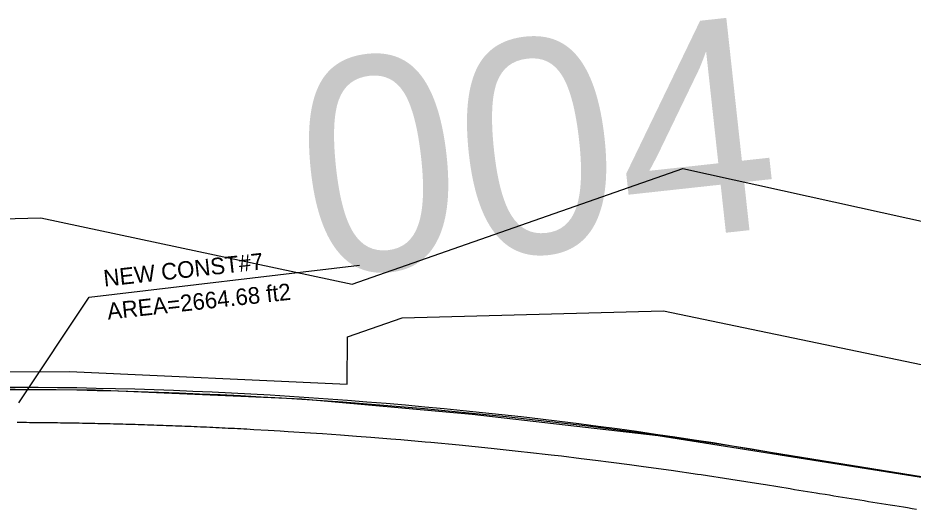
# Model space of a CAD drawing. Extents: x 1509538 to 1510847, y 401283 to 402022.
# Drawn here: x 1510184.5 to 1510335.3, y 401706.3 to 401789.3 of the extents above; entities that cross this region are included whole.
import ezdxf

# ---------------------------------------------------------------- set-up
doc = ezdxf.new("R2010")
doc.units = 0
for name, color, linetype in [('LAWE_P_T', 7, 'Continuous'), ('Level 14', 7, 'Continuous'), ('Level 22', 7, 'Continuous'), ('Level 24', 7, 'Continuous'), ('Level 3', 7, 'Continuous')]:
    doc.layers.add(name, color=color, linetype=linetype)

msp = doc.modelspace()

# ---------------------------------------------------------------- linework, layer by layer
at = {"layer": 'LAWE_P_T'}
msp.add_lwpolyline([(1510184.66, 401724.34), (1510196.5, 401742.17), (1510242.07, 401747.56)], dxfattribs=at)
at = {"layer": 'Level 14'}
msp.add_line((1510311.33, 401716), (1510436.45, 401695.69), dxfattribs=at)
msp.add_arc((1510179.87, 400906.1), 820.5, 80.78048, 96.2219, dxfattribs=at)
at = {"layer": 'Level 22'}
msp.add_lwpolyline([(1510163.27, 401729.57), (1510193.23, 401729.63), (1510240, 401727.48), (1510240.05, 401735.46), (1510249.26, 401738.71), (1510293.27, 401739.88), (1510404.63, 401716.65), (1510416.62, 401714.21), (1510414.07, 401699.18), (1510406.28, 401635.45), (1510397.88, 401621.86), (1510377.81, 401611.86), (1510331.03, 401618.95), (1510273.83, 401631.15), (1510231.99, 401640.14), (1510237.83, 401669.36), (1510405.63, 401640.09), (1510412.68, 401699.55), (1510362.56, 401707.65), (1510292.37, 401718.82), (1510261.04, 401722.38), (1510232.33, 401724.97), (1510197.61, 401726.48), (1510164.02, 401726.59)], dxfattribs=at)
at = {"layer": 'Level 24'}
msp.add_lwpolyline([(1509965.11, 401725.82), (1510041.03, 401773.36), (1510042.45, 401774.24), (1510071.47, 401767.53), (1510092.26, 401761.29), (1510106.06, 401761.59), (1510116.39, 401753.93), (1510166.17, 401754.62), (1510168.79, 401755.02), (1510188.36, 401755.57), (1510240.81, 401744.39), (1510296.54, 401763.85), (1510359.87, 401749.85), (1510436.07, 401732.12)], dxfattribs=at)
at = {"layer": 'Level 3'}
for p, q in [((1510184.39, 401721.09), (1510184.91, 401721.09)), ((1510184.91, 401721.09), (1510185.43, 401721.08)), ((1510185.43, 401721.08), (1510185.96, 401721.08)), ((1510185.96, 401721.08), (1510186.48, 401721.07)), ((1510186.48, 401721.07), (1510187, 401721.07)), ((1510187, 401721.07), (1510187.53, 401721.07)), ((1510187.53, 401721.07), (1510188.05, 401721.06)), ((1510188.05, 401721.06), (1510188.57, 401721.05)), ((1510188.57, 401721.05), (1510189.1, 401721.05)), ((1510189.1, 401721.05), (1510189.62, 401721.04)), ((1510189.62, 401721.04), (1510190.14, 401721.04)), ((1510190.14, 401721.04), (1510190.67, 401721.03)), ((1510190.67, 401721.03), (1510191.19, 401721.02)), ((1510191.19, 401721.02), (1510191.71, 401721.01)), ((1510191.71, 401721.01), (1510192.24, 401721.01)), ((1510192.24, 401721.01), (1510192.76, 401721)), ((1510192.76, 401721), (1510193.28, 401720.99)), ((1510193.28, 401720.99), (1510193.81, 401720.98)), ((1510193.81, 401720.98), (1510194.33, 401720.97)), ((1510194.33, 401720.97), (1510194.86, 401720.96)), ((1510194.86, 401720.96), (1510195.38, 401720.95)), ((1510195.38, 401720.95), (1510195.9, 401720.94)), ((1510195.9, 401720.94), (1510196.43, 401720.93)), ((1510196.43, 401720.93), (1510196.95, 401720.92)), ((1510196.95, 401720.92), (1510197.47, 401720.91)), ((1510197.47, 401720.91), (1510198, 401720.9)), ((1510198, 401720.9), (1510198.52, 401720.89)), ((1510198.52, 401720.89), (1510199.04, 401720.88)), ((1510199.04, 401720.88), (1510199.57, 401720.86)), ((1510199.57, 401720.86), (1510200.09, 401720.85)), ((1510200.09, 401720.85), (1510200.61, 401720.84)), ((1510200.61, 401720.84), (1510201.14, 401720.82)), ((1510201.14, 401720.82), (1510201.66, 401720.81)), ((1510201.66, 401720.81), (1510202.18, 401720.8)), ((1510202.18, 401720.8), (1510202.7, 401720.78)), ((1510202.7, 401720.78), (1510203.23, 401720.77)), ((1510203.23, 401720.77), (1510203.75, 401720.75)), ((1510203.75, 401720.75), (1510204.27, 401720.74)), ((1510204.27, 401720.74), (1510204.8, 401720.72)), ((1510204.8, 401720.72), (1510205.32, 401720.7)), ((1510205.32, 401720.7), (1510205.84, 401720.69)), ((1510205.84, 401720.69), (1510206.37, 401720.67)), ((1510206.37, 401720.67), (1510206.89, 401720.65)), ((1510206.89, 401720.65), (1510207.41, 401720.64)), ((1510207.41, 401720.64), (1510207.94, 401720.62)), ((1510207.94, 401720.62), (1510208.46, 401720.6)), ((1510208.46, 401720.6), (1510208.98, 401720.58)), ((1510208.98, 401720.58), (1510209.51, 401720.56)), ((1510209.51, 401720.56), (1510210.03, 401720.54)), ((1510210.03, 401720.54), (1510210.55, 401720.52)), ((1510210.55, 401720.52), (1510211.08, 401720.5)), ((1510211.08, 401720.5), (1510211.6, 401720.48)), ((1510211.6, 401720.48), (1510212.12, 401720.46)), ((1510212.12, 401720.46), (1510212.64, 401720.44)), ((1510212.64, 401720.44), (1510213.17, 401720.42)), ((1510213.17, 401720.42), (1510213.69, 401720.4)), ((1510213.69, 401720.4), (1510214.21, 401720.38)), ((1510214.21, 401720.38), (1510214.74, 401720.35)), ((1510214.74, 401720.35), (1510215.26, 401720.33)), ((1510215.26, 401720.33), (1510215.78, 401720.31)), ((1510215.78, 401720.31), (1510216.31, 401720.29)), ((1510216.31, 401720.29), (1510216.83, 401720.26)), ((1510216.83, 401720.26), (1510217.35, 401720.24)), ((1510217.35, 401720.24), (1510217.87, 401720.22)), ((1510217.87, 401720.22), (1510218.4, 401720.19)), ((1510218.4, 401720.19), (1510218.92, 401720.16)), ((1510218.92, 401720.16), (1510219.44, 401720.14)), ((1510219.44, 401720.14), (1510219.97, 401720.11)), ((1510219.97, 401720.11), (1510220.49, 401720.09)), ((1510220.49, 401720.09), (1510221.01, 401720.06)), ((1510221.01, 401720.06), (1510221.53, 401720.04)), ((1510221.53, 401720.04), (1510222.06, 401720.01)), ((1510222.06, 401720.01), (1510222.58, 401719.98)), ((1510222.58, 401719.98), (1510223.1, 401719.95)), ((1510223.1, 401719.95), (1510223.63, 401719.93)), ((1510223.63, 401719.93), (1510224.29, 401719.89)), ((1510224.29, 401719.89), (1510226.68, 401719.76)), ((1510226.68, 401719.76), (1510228.71, 401719.64)), ((1510228.71, 401719.64), (1510230.06, 401719.55)), ((1510230.06, 401719.55), (1510233.79, 401719.32)), ((1510233.79, 401719.32), (1510235.83, 401719.18)), ((1510235.83, 401719.18), (1510238.88, 401718.96)), ((1510238.88, 401718.96), (1510241.59, 401718.76)), ((1510241.59, 401718.76), (1510243.96, 401718.58)), ((1510243.96, 401718.58), (1510247.36, 401718.3)), ((1510247.36, 401718.3), (1510249.03, 401718.16)), ((1510249.03, 401718.16), (1510253.11, 401717.8)), ((1510253.11, 401717.8), (1510254.11, 401717.71)), ((1510254.11, 401717.71), (1510258.87, 401717.26)), ((1510258.87, 401717.26), (1510264.25, 401716.72)), ((1510264.25, 401716.72), (1510269.31, 401716.18)), ((1510269.31, 401716.18), (1510270.37, 401716.06)), ((1510270.37, 401716.06), (1510274.37, 401715.6)), ((1510436.45, 401695.69), (1510311.33, 401716)), ((1510274.37, 401715.6), (1510276.11, 401715.4)), ((1510276.11, 401715.4), (1510279.43, 401715)), ((1510279.43, 401715), (1510281.85, 401714.7)), ((1510281.85, 401714.7), (1510284.48, 401714.36)), ((1510284.48, 401714.36), (1510287.58, 401713.95)), ((1510287.58, 401713.95), (1510289.53, 401713.69)), ((1510289.53, 401713.69), (1510293.3, 401713.17)), ((1510293.3, 401713.17), (1510294.58, 401712.99)), ((1510294.58, 401712.99), (1510299.03, 401712.34)), ((1510299.03, 401712.34), (1510299.62, 401712.26)), ((1510299.62, 401712.26), (1510304.65, 401711.49)), ((1510304.65, 401711.49), (1510309.69, 401710.7)), ((1510309.69, 401710.7), (1510310.45, 401710.57)), ((1510310.45, 401710.57), (1510314.63, 401709.89)), ((1510314.63, 401709.89), (1510315.37, 401709.77)), ((1510315.37, 401709.77), (1510316.1, 401709.65)), ((1510316.1, 401709.65), (1510316.83, 401709.54)), ((1510316.83, 401709.54), (1510317.57, 401709.42)), ((1510317.57, 401709.42), (1510318.3, 401709.3)), ((1510318.3, 401709.3), (1510319.03, 401709.18)), ((1510319.03, 401709.18), (1510319.57, 401709.09)), ((1510319.57, 401709.09), (1510320.5, 401708.94)), ((1510320.5, 401708.94), (1510321.23, 401708.82)), ((1510321.23, 401708.82), (1510321.96, 401708.7)), ((1510321.96, 401708.7), (1510322.7, 401708.59)), ((1510322.7, 401708.59), (1510323.43, 401708.47)), ((1510323.43, 401708.47), (1510324.16, 401708.35)), ((1510324.16, 401708.35), (1510324.9, 401708.23)), ((1510324.9, 401708.23), (1510325.63, 401708.11)), ((1510325.63, 401708.11), (1510326.36, 401707.99)), ((1510326.36, 401707.99), (1510327.1, 401707.87)), ((1510327.1, 401707.87), (1510327.83, 401707.75)), ((1510327.83, 401707.75), (1510328.56, 401707.63)), ((1510328.56, 401707.63), (1510329.29, 401707.51)), ((1510329.29, 401707.51), (1510330.03, 401707.4)), ((1510330.03, 401707.4), (1510330.76, 401707.28)), ((1510330.76, 401707.28), (1510331.49, 401707.16)), ((1510331.49, 401707.16), (1510332.23, 401707.04)), ((1510332.23, 401707.04), (1510332.96, 401706.92)), ((1510332.96, 401706.92), (1510333.69, 401706.8)), ((1510333.69, 401706.8), (1510334.38, 401706.69)), ((1510334.38, 401706.69), (1510335.16, 401706.56)), ((1510335.16, 401706.56), (1510335.89, 401706.44))]:
    msp.add_line(p, q, dxfattribs=at)
msp.add_lwpolyline([(1510184.39, 401721.09), (1510184.91, 401721.09), (1510185.43, 401721.08), (1510185.96, 401721.08), (1510186.48, 401721.07), (1510187, 401721.07), (1510187.53, 401721.07), (1510188.05, 401721.06), (1510188.57, 401721.05), (1510189.1, 401721.05), (1510189.62, 401721.04), (1510190.14, 401721.04), (1510190.67, 401721.03), (1510191.19, 401721.02), (1510191.71, 401721.01), (1510192.24, 401721.01), (1510192.76, 401721), (1510193.28, 401720.99), (1510193.81, 401720.98), (1510194.33, 401720.97), (1510194.86, 401720.96), (1510195.38, 401720.95), (1510195.9, 401720.94), (1510196.43, 401720.93), (1510196.95, 401720.92), (1510197.47, 401720.91), (1510198, 401720.9), (1510198.52, 401720.89), (1510199.04, 401720.88), (1510199.57, 401720.86), (1510200.09, 401720.85), (1510200.61, 401720.84), (1510201.14, 401720.82), (1510201.66, 401720.81), (1510202.18, 401720.8), (1510202.7, 401720.78), (1510203.23, 401720.77), (1510203.75, 401720.75), (1510204.27, 401720.74), (1510204.8, 401720.72), (1510205.32, 401720.7), (1510205.84, 401720.69), (1510206.37, 401720.67), (1510206.89, 401720.65), (1510207.41, 401720.64), (1510207.94, 401720.62), (1510208.46, 401720.6), (1510208.98, 401720.58), (1510209.51, 401720.56), (1510210.03, 401720.54), (1510210.55, 401720.52), (1510211.08, 401720.5), (1510211.6, 401720.48), (1510212.12, 401720.46), (1510212.64, 401720.44), (1510213.17, 401720.42), (1510213.69, 401720.4), (1510214.21, 401720.38), (1510214.74, 401720.35), (1510215.26, 401720.33), (1510215.78, 401720.31), (1510216.31, 401720.29), (1510216.83, 401720.26), (1510217.35, 401720.24), (1510217.87, 401720.22), (1510218.4, 401720.19), (1510218.92, 401720.16), (1510219.44, 401720.14), (1510219.97, 401720.11), (1510220.49, 401720.09), (1510221.01, 401720.06), (1510221.53, 401720.04), (1510222.06, 401720.01), (1510222.58, 401719.98), (1510223.1, 401719.95), (1510223.63, 401719.93), (1510224.29, 401719.89), (1510226.68, 401719.76), (1510228.71, 401719.64), (1510230.06, 401719.55), (1510233.79, 401719.32), (1510235.83, 401719.18), (1510238.88, 401718.96), (1510241.59, 401718.76), (1510243.96, 401718.58), (1510247.36, 401718.3), (1510249.03, 401718.16), (1510253.11, 401717.8), (1510254.11, 401717.71), (1510258.87, 401717.26), (1510264.25, 401716.72), (1510269.31, 401716.18), (1510270.37, 401716.06), (1510274.37, 401715.6), (1510276.11, 401715.4), (1510279.43, 401715), (1510281.85, 401714.7), (1510284.48, 401714.36), (1510287.58, 401713.95), (1510289.53, 401713.69), (1510293.3, 401713.17), (1510294.58, 401712.99), (1510299.03, 401712.34), (1510299.62, 401712.26), (1510304.65, 401711.49), (1510309.69, 401710.7), (1510310.45, 401710.57), (1510314.63, 401709.89), (1510315.37, 401709.77), (1510316.1, 401709.65), (1510316.83, 401709.54), (1510317.57, 401709.42), (1510318.3, 401709.3), (1510319.03, 401709.18), (1510319.57, 401709.09), (1510320.5, 401708.94), (1510321.23, 401708.82), (1510321.96, 401708.7), (1510322.7, 401708.59), (1510323.43, 401708.47), (1510324.16, 401708.35), (1510324.9, 401708.23), (1510325.63, 401708.11), (1510326.36, 401707.99), (1510327.1, 401707.87), (1510327.83, 401707.75), (1510328.56, 401707.63), (1510329.29, 401707.51), (1510330.03, 401707.4), (1510330.76, 401707.28), (1510331.49, 401707.16), (1510332.23, 401707.04), (1510332.96, 401706.92), (1510333.69, 401706.8), (1510334.38, 401706.69), (1510335.16, 401706.56), (1510335.89, 401706.44)], dxfattribs=at)
msp.add_arc((1510181.41, 400951.86), 775.11, 80.35098, 95.7924, dxfattribs=at)

# ---------------------------------------------------------------- texts
at = {"layer": 'LAWE_P_T'}
for s, p in [('NEW CONST#7', (1510199.09, 401743.94)), ('AREA=2664.68 ft2', (1510199.7, 401738.38))]:
    msp.add_text(s, height=2.8, rotation=6.2219, dxfattribs=at).set_placement(p)
at = {"layer": 'Level 3'}
msp.add_text('004', height=36, rotation=6.2215, dxfattribs=at).set_placement((1510233.95, 401745.42))

doc.saveas('drawing.dxf')
